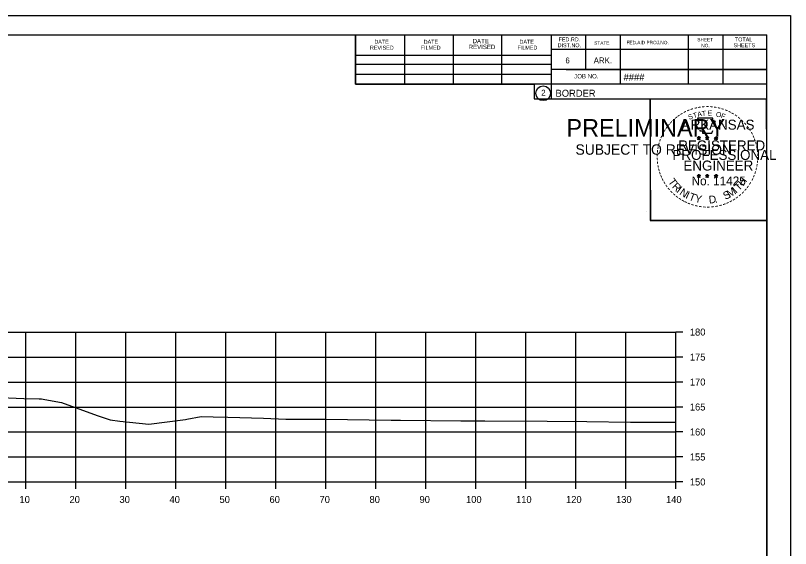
# Model space of a CAD drawing. Extents: x 1368503 to 1373085, y 379840 to 381833.
# Drawn here: x 1372930 to 1373085, y 381561.7 to 381668.3 of the extents above; entities that cross this region are included whole.
import ezdxf

# ---------------------------------------------------------------- set-up
doc = ezdxf.new("R2010")
doc.units = 0
for name, color, linetype in [('S_BRIDGE', 7, 'Continuous'), ('S_EDGE_PAVEMENT', 7, 'Continuous'), ('S_LANDSCAPING', 7, 'Continuous'), ('S_MISC_BOUNDARY', 7, 'Continuous'), ('S_MISC_BOUNDARY_ANNOT', 7, 'Continuous'), ('S_PHOTO_CENTERS', 7, 'Continuous'), ('S_PHOTO_NOTES', 7, 'Continuous'), ('S_TRAILS', 7, 'Continuous')]:
    doc.layers.add(name, color=color, linetype=linetype)

msp = doc.modelspace()

# ---------------------------------------------------------------- linework, layer by layer
at = {"layer": 'S_BRIDGE'}
for p, q in [((1372764.08, 381664.44), (1373080.26, 381664.44)), ((1372998, 381654.56), (1372998, 381664.44)), ((1373037.16, 381664.44), (1373037.16, 381651.64)), ((1373044, 381664.44), (1373044, 381657.5)), ((1373050.94, 381664.44), (1373050.94, 381654.56)), ((1373064.52, 381664.44), (1373064.52, 381654.56)), ((1373071.46, 381664.44), (1373071.46, 381654.56)), ((1373080.26, 381458.98), (1373080.26, 381664.44)), ((1373007.86, 381654.56), (1373007.86, 381664.24)), ((1373017.62, 381654.56), (1373017.62, 381664.24)), ((1373027.3, 381654.56), (1373027.3, 381664.24)), ((1373080.26, 381661.5), (1373037.16, 381661.5)), ((1373080.26, 381661.52), (1373080.26, 381661.52)), ((1372998, 381660.42), (1373037.16, 381660.42)), ((1372998, 381658.56), (1373037.16, 381658.56)), ((1372998, 381654.56), (1372998, 381656.62)), ((1372998, 381656.62), (1373037.16, 381656.62)), ((1373080.26, 381657.5), (1373037.16, 381657.5)), ((1373040.12, 381657.5), (1373080.26, 381657.5)), ((1373080.26, 381654.56), (1372998, 381654.56)), ((1373037.16, 381651.64), (1373080.26, 381651.64))]:
    msp.add_line(p, q, dxfattribs=at)
msp.add_circle((1373035.55, 381652.77), 1.47, dxfattribs=at)
at = {"layer": 'S_EDGE_PAVEMENT'}
for p, q in [((1373062.08, 381574.98), (1373062.08, 381604.98)), ((1373063.48, 381604.98), (1373062.08, 381604.98)), ((1373063.48, 381599.98), (1373062.08, 381599.98)), ((1373063.48, 381594.98), (1373062.08, 381594.98)), ((1373063.48, 381589.98), (1373062.08, 381589.98)), ((1373063.48, 381584.98), (1373062.08, 381584.98)), ((1373063.48, 381579.98), (1373062.08, 381579.98)), ((1372782.08, 381574.98), (1373062.08, 381574.98)), ((1372932.08, 381573.58), (1372932.08, 381574.98)), ((1372942.08, 381573.58), (1372942.08, 381574.98)), ((1372952.08, 381573.58), (1372952.08, 381574.98)), ((1372962.08, 381573.58), (1372962.08, 381574.98)), ((1372972.08, 381573.58), (1372972.08, 381574.98)), ((1372982.08, 381573.58), (1372982.08, 381574.98)), ((1372992.08, 381573.58), (1372992.08, 381574.98)), ((1373002.08, 381573.58), (1373002.08, 381574.98)), ((1373012.08, 381573.58), (1373012.08, 381574.98)), ((1373022.08, 381573.58), (1373022.08, 381574.98)), ((1373032.08, 381573.58), (1373032.08, 381574.98)), ((1373042.08, 381573.58), (1373042.08, 381574.98)), ((1373052.08, 381573.58), (1373052.08, 381574.98)), ((1373062.08, 381573.58), (1373062.08, 381574.98)), ((1373063.48, 381574.98), (1373062.08, 381574.98))]:
    msp.add_line(p, q, dxfattribs=at)
at = {"layer": 'S_LANDSCAPING'}
for p, q in [((1373066.35, 381643.89), (1373066.7, 381643.78)), ((1373066.35, 381643.89), (1373066.6, 381643.85)), ((1373066.35, 381643.89), (1373066.58, 381643.77)), ((1373066.48, 381643.48), (1373066.7, 381643.78)), ((1373066.48, 381643.48), (1373066.61, 381643.73)), ((1373066.48, 381643.48), (1373066.69, 381643.7)), ((1373066.7, 381644.15), (1373066.65, 381643.89)), ((1373066.91, 381643.48), (1373066.69, 381643.7)), ((1373066.7, 381643.78), (1373066.7, 381644.15)), ((1373066.7, 381644.15), (1373066.74, 381643.9)), ((1373067.04, 381643.89), (1373066.7, 381643.78)), ((1373066.91, 381643.48), (1373066.7, 381643.78)), ((1373067.04, 381643.89), (1373066.76, 381643.84)), ((1373066.91, 381643.48), (1373066.77, 381643.78)), ((1373067.04, 381643.89), (1373066.84, 381643.79)), ((1373068.02, 381643.89), (1373068.37, 381643.78)), ((1373068.02, 381643.89), (1373068.27, 381643.85)), ((1373068.02, 381643.89), (1373068.25, 381643.77)), ((1373068.15, 381643.48), (1373068.37, 381643.78)), ((1373068.15, 381643.48), (1373068.28, 381643.73)), ((1373068.15, 381643.48), (1373068.36, 381643.7)), ((1373068.37, 381644.15), (1373068.32, 381643.89)), ((1373068.58, 381643.48), (1373068.36, 381643.7)), ((1373068.37, 381643.78), (1373068.37, 381644.15)), ((1373068.37, 381644.15), (1373068.41, 381643.9)), ((1373068.71, 381643.89), (1373068.37, 381643.78)), ((1373068.58, 381643.48), (1373068.37, 381643.78)), ((1373068.71, 381643.89), (1373068.43, 381643.84)), ((1373068.58, 381643.48), (1373068.44, 381643.78)), ((1373068.71, 381643.89), (1373068.51, 381643.79)), ((1373069.78, 381643.88), (1373070.13, 381643.77)), ((1373069.78, 381643.88), (1373070.03, 381643.84)), ((1373069.78, 381643.88), (1373070.02, 381643.76)), ((1373069.91, 381643.47), (1373070.13, 381643.77)), ((1373069.91, 381643.47), (1373070.04, 381643.72)), ((1373069.91, 381643.47), (1373070.13, 381643.69)), ((1373070.13, 381644.13), (1373070.09, 381643.88)), ((1373070.13, 381643.77), (1373070.13, 381644.13)), ((1373070.13, 381644.13), (1373070.18, 381643.88)), ((1373070.48, 381643.88), (1373070.13, 381643.77)), ((1373070.34, 381643.47), (1373070.13, 381643.77)), ((1373070.34, 381643.47), (1373070.13, 381643.69)), ((1373070.48, 381643.88), (1373070.19, 381643.83)), ((1373070.34, 381643.47), (1373070.21, 381643.76)), ((1373070.48, 381643.88), (1373070.27, 381643.78)), ((1373066.69, 381636.57), (1373066.65, 381636.32)), ((1373066.69, 381636.21), (1373066.69, 381636.57)), ((1373066.69, 381636.57), (1373066.74, 381636.32)), ((1373068.36, 381636.57), (1373068.32, 381636.32)), ((1373068.36, 381636.21), (1373068.36, 381636.57)), ((1373068.36, 381636.57), (1373068.41, 381636.32)), ((1373070.13, 381636.56), (1373070.09, 381636.31)), ((1373070.13, 381636.2), (1373070.13, 381636.56)), ((1373070.13, 381636.56), (1373070.18, 381636.31)), ((1373066.34, 381636.32), (1373066.69, 381636.21)), ((1373066.34, 381636.32), (1373066.6, 381636.27)), ((1373066.34, 381636.32), (1373066.58, 381636.2)), ((1373066.48, 381635.91), (1373066.69, 381636.21)), ((1373066.48, 381635.91), (1373066.6, 381636.16)), ((1373066.48, 381635.91), (1373066.69, 381636.13)), ((1373067.04, 381636.32), (1373066.69, 381636.21)), ((1373066.9, 381635.91), (1373066.69, 381636.21)), ((1373066.9, 381635.91), (1373066.69, 381636.13)), ((1373067.04, 381636.32), (1373066.75, 381636.27)), ((1373066.9, 381635.91), (1373066.77, 381636.2)), ((1373067.04, 381636.32), (1373066.83, 381636.22)), ((1373068.01, 381636.32), (1373068.36, 381636.21)), ((1373068.01, 381636.32), (1373068.26, 381636.27)), ((1373068.01, 381636.32), (1373068.25, 381636.2)), ((1373068.14, 381635.91), (1373068.36, 381636.21)), ((1373068.14, 381635.91), (1373068.27, 381636.16)), ((1373068.14, 381635.91), (1373068.36, 381636.13)), ((1373068.71, 381636.32), (1373068.36, 381636.21)), ((1373068.57, 381635.91), (1373068.36, 381636.21)), ((1373068.57, 381635.91), (1373068.36, 381636.13)), ((1373068.71, 381636.32), (1373068.42, 381636.27)), ((1373068.57, 381635.91), (1373068.44, 381636.2)), ((1373068.71, 381636.32), (1373068.5, 381636.22)), ((1373069.78, 381636.31), (1373070.13, 381636.2)), ((1373069.78, 381636.31), (1373070.03, 381636.26)), ((1373069.78, 381636.31), (1373070.02, 381636.19)), ((1373069.91, 381635.9), (1373070.13, 381636.2)), ((1373069.91, 381635.9), (1373070.04, 381636.15)), ((1373069.91, 381635.9), (1373070.13, 381636.12)), ((1373070.47, 381636.31), (1373070.13, 381636.2)), ((1373070.34, 381635.9), (1373070.13, 381636.2)), ((1373070.34, 381635.9), (1373070.13, 381636.12)), ((1373070.47, 381636.31), (1373070.19, 381636.26)), ((1373070.34, 381635.9), (1373070.2, 381636.19)), ((1373070.47, 381636.31), (1373070.27, 381636.21))]:
    msp.add_line(p, q, dxfattribs=at)
for points in [[(1373066.39, 381647.77), (1373066.66, 381646.94)], [(1373069.9, 381646.85), (1373070.04, 381647.13), (1373069.36, 381647.11), (1373069.5, 381647.77), (1373066.39, 381647.77)], [(1373066.88, 381645.35), (1373066.88, 381645.26), (1373067.44, 381645.24), (1373067.39, 381644.77), (1373069.26, 381644.77), (1373069.46, 381645.3)], [(1373066.7, 381644.15), (1373066.91, 381643.48), (1373066.35, 381643.89), (1373067.04, 381643.89), (1373066.48, 381643.48), (1373066.7, 381644.15)], [(1373068.37, 381644.15), (1373068.58, 381643.48), (1373068.02, 381643.89), (1373068.71, 381643.89), (1373068.15, 381643.48), (1373068.37, 381644.15)], [(1373070.13, 381644.13), (1373070.34, 381643.47), (1373069.78, 381643.88), (1373070.48, 381643.88), (1373069.91, 381643.47), (1373070.13, 381644.13)], [(1373066.69, 381636.57), (1373066.9, 381635.91), (1373066.34, 381636.32), (1373067.04, 381636.32), (1373066.48, 381635.91), (1373066.69, 381636.57)], [(1373068.36, 381636.57), (1373068.57, 381635.91), (1373068.01, 381636.32), (1373068.71, 381636.32), (1373068.14, 381635.91), (1373068.36, 381636.57)], [(1373070.13, 381636.56), (1373070.34, 381635.9), (1373069.78, 381636.31), (1373070.47, 381636.31), (1373069.91, 381635.9), (1373070.13, 381636.56)]]:
    msp.add_lwpolyline(points, dxfattribs=at)
for centre, radius in [((1373066.69, 381643.78), 0.172), ((1373066.69, 381643.78), 0.145), ((1373066.69, 381643.78), 0.116), ((1373066.69, 381643.78), 0.0991), ((1373066.69, 381643.78), 0.0747), ((1373066.69, 381643.78), 0.0495), ((1373066.69, 381643.78), 0.0296), ((1373068.36, 381643.78), 0.172), ((1373068.36, 381643.78), 0.145), ((1373068.36, 381643.78), 0.116), ((1373068.36, 381643.78), 0.0991), ((1373068.36, 381643.78), 0.0747), ((1373068.36, 381643.78), 0.0495), ((1373068.36, 381643.78), 0.0296), ((1373070.13, 381643.77), 0.172), ((1373070.13, 381643.77), 0.145), ((1373070.13, 381643.77), 0.116), ((1373070.13, 381643.77), 0.0991), ((1373070.13, 381643.77), 0.0747), ((1373070.13, 381643.77), 0.0495), ((1373070.13, 381643.77), 0.0296), ((1373066.69, 381636.21), 0.172), ((1373066.69, 381636.21), 0.145), ((1373066.69, 381636.21), 0.116), ((1373066.69, 381636.21), 0.0991), ((1373066.69, 381636.21), 0.0747), ((1373066.69, 381636.21), 0.0495), ((1373066.69, 381636.21), 0.0296), ((1373068.36, 381636.21), 0.172), ((1373068.36, 381636.21), 0.145), ((1373068.36, 381636.21), 0.116), ((1373068.36, 381636.21), 0.0991), ((1373068.36, 381636.21), 0.0747), ((1373068.36, 381636.21), 0.0495), ((1373068.36, 381636.21), 0.0296), ((1373070.13, 381636.2), 0.172), ((1373070.13, 381636.2), 0.145), ((1373070.13, 381636.2), 0.116), ((1373070.13, 381636.2), 0.0991), ((1373070.13, 381636.2), 0.0747), ((1373070.13, 381636.2), 0.0495), ((1373070.13, 381636.2), 0.0296)]:
    msp.add_circle(centre, radius, dxfattribs=at)
at = {"layer": 'S_MISC_BOUNDARY'}
msp.add_lwpolyline([(1372925.58, 381591.97), (1372931.69, 381591.71), (1372934.75, 381591.62), (1372935.23, 381591.61), (1372935.9, 381591.48), (1372939.23, 381590.85), (1372946.36, 381588.31), (1372948.93, 381587.39), (1372950.86, 381587.18), (1372956.7, 381586.56), (1372963.52, 381587.41), (1372964.02, 381587.48), (1372964.26, 381587.52), (1372967.14, 381588.05), (1372969.57, 381588), (1372972.48, 381587.95), (1372979.64, 381587.72), (1372984.07, 381587.56), (1372991.26, 381587.56), (1372991.61, 381587.56), (1372992.02, 381587.56), (1373005.13, 381587.35), (1373007.03, 381587.35), (1373019.09, 381587.24), (1373023.86, 381587.21), (1373036.36, 381587.15), (1373044.26, 381587.07), (1373053.03, 381586.97), (1373062.08, 381586.92)], dxfattribs=at)
at = {"layer": 'S_PHOTO_CENTERS'}
for p, q in [((1372782.08, 381604.98), (1373062.08, 381604.98)), ((1372932.08, 381574.98), (1372932.08, 381604.98)), ((1372942.08, 381574.98), (1372942.08, 381604.98)), ((1372952.08, 381574.98), (1372952.08, 381604.98)), ((1372962.08, 381574.98), (1372962.08, 381604.98)), ((1372972.08, 381574.98), (1372972.08, 381604.98)), ((1372982.08, 381574.98), (1372982.08, 381604.98)), ((1372992.08, 381574.98), (1372992.08, 381604.98)), ((1373002.08, 381574.98), (1373002.08, 381604.98)), ((1373012.08, 381574.98), (1373012.08, 381604.98)), ((1373022.08, 381574.98), (1373022.08, 381604.98)), ((1373032.08, 381574.98), (1373032.08, 381604.98)), ((1373042.08, 381574.98), (1373042.08, 381604.98)), ((1373052.08, 381574.98), (1373052.08, 381604.98)), ((1373062.08, 381574.98), (1373062.08, 381604.98)), ((1372782.08, 381599.98), (1373062.08, 381599.98)), ((1372782.08, 381594.98), (1373062.08, 381594.98)), ((1372782.08, 381589.98), (1373062.08, 381589.98)), ((1372782.08, 381584.98), (1373062.08, 381584.98)), ((1372782.08, 381579.98), (1373062.08, 381579.98)), ((1372782.08, 381574.98), (1373062.08, 381574.98))]:
    msp.add_line(p, q, dxfattribs=at)
at = {"layer": 'S_PHOTO_NOTES'}
for p, q in [((1372751.68, 381668.33), (1373085.01, 381668.33)), ((1373056.3, 381629.18), (1373056.3, 381629.18))]:
    msp.add_line(p, q, dxfattribs=at)
for points in [[(1372751.67, 381668.33), (1373085.01, 381668.33), (1373085.01, 381454.99), (1372751.67, 381454.99)], [(1372998, 381664.44), (1372998, 381654.56), (1373033.73, 381654.56), (1373033.73, 381651.64), (1373056.93, 381651.64), (1373056.93, 381627.3), (1373080.26, 381627.3), (1373080.26, 381458.98), (1372764.08, 381458.98), (1372764.08, 381664.44)], [(1373056.93, 381651.64), (1373080.14, 381651.64), (1373080.26, 381627.3), (1373057.05, 381627.3)]]:
    msp.add_lwpolyline(points, close=True, dxfattribs=at)

# ---------------------------------------------------------------- texts
at = {"layer": 'S_BRIDGE'}
for s, height, p in [('DATE', 0.782, (1373001.8, 381662.68)), ('DATE', 0.782, (1373011.66, 381662.68)), ('DATE', 0.879, (1373021.44, 381662.78)), ('DATE', 0.782, (1373030.82, 381662.68)), ('FED.RD.', 0.782, (1373038.64, 381663.16)), ('STATE', 0.684, (1373045.76, 381662.48)), ('FED.AID PROJ.NO.', 0.684, (1373052.22, 381662.58)), ('SHEET', 0.684, (1373066.38, 381663.16)), ('TOTAL', 0.782, (1373073.9, 381663.16)), ('REVISED', 0.782, (1373000.92, 381661.5)), ('FILMED', 0.782, (1373011.08, 381661.5)), ('REVISED', 0.879, (1373020.66, 381661.6)), ('FILMED', 0.782, (1373030.42, 381661.5)), ('DIST.NO.', 0.782, (1373038.44, 381661.98)), ('NO.', 0.684, (1373067.16, 381661.98)), ('SHEETS', 0.782, (1373073.62, 381661.98)), ('6', 1.17, (1373040, 381658.76)), ('ARK.', 1.172, (1373045.66, 381658.76)), ('JOB NO.', 0.879, (1373041.76, 381655.74)), ('####', 1.4, (1373051.64, 381655.3)), ('BORDER', 1.4, (1373038.02, 381652.07)), ('2', 1.17, (1373035.17, 381652.29))]:
    msp.add_text(s, height=height, rotation=360, dxfattribs=at).set_placement(p)
at = {"layer": 'S_LANDSCAPING'}
for s, height, rotation, p in [('-', 1.6, 34.0636, (1373063.27, 381647.94)), ('-', 1.6, 28.7918, (1373063.87, 381648.31)), ('-', 1.6, 24.3072, (1373064.5, 381648.63)), ('-', 1.6, 19.1761, (1373065.14, 381648.9)), ('T', 1, 16.4036, (1373065.66, 381647.78)), ('-', 1.6, 13.6301, (1373065.89, 381649.14)), ('A', 1, 11.2132, (1373066.48, 381648.03)), ('-', 1.6, 10.2193, (1373066.56, 381649.3)), ('T', 1, 6.0228, (1373067.33, 381648.2)), ('-', 1.6, 5.8968, (1373067.29, 381649.41)), ('-', 1.6, 0.1862, (1373068.06, 381649.48)), ('E', 1, 0.8323, (1373068.44, 381648.31)), ('-', 1.6, 357.743, (1373068.79, 381649.47)), ('-', 1.6, 352.1617, (1373069.53, 381649.41)), ('O', 1, 350.4515, (1373070.04, 381648.1)), ('-', 1.6, 347.2049, (1373070.25, 381649.3)), ('-', 1.6, 342.3362, (1373070.89, 381649.14)), ('-', 1.6, 337.8551, (1373071.62, 381648.92)), ('-', 1.6, 334.1211, (1373072.25, 381648.65)), ('-', 1.6, 329.6409, (1373072.83, 381648.37)), ('-', 1.6, 42.9622, (1373061.78, 381646.75)), ('-', 1.6, 38.9507, (1373062.22, 381647.17)), ('-', 1.6, 36.2317, (1373062.69, 381647.55)), ('ARKANSAS', 2, 360, (1373063.24, 381645.48)), ('S', 1, 21.594, (1373064.74, 381647.45)), ('F', 1, 340.0707, (1373070.99, 381647.87)), ('-', 1.6, 325.8627, (1373073.47, 381648.01)), ('-', 1.6, 320.5297, (1373074.08, 381647.58)), ('-', 1.6, 315.5786, (1373074.68, 381647.09)), ('-', 1.6, 54.2325, (1373060.52, 381645.22)), ('-', 1.6, 50.6142, (1373060.93, 381645.79)), ('-', 1.6, 48.423, (1373061.34, 381646.27)), ('-', 1.6, 309.8797, (1373075.25, 381646.54)), ('-', 1.6, 306.6522, (1373075.78, 381645.94)), ('-', 1.6, 67.7743, (1373059.62, 381643.47)), ('-', 1.6, 62.8713, (1373059.88, 381644.08)), ('-', 1.6, 58.0706, (1373060.2, 381644.69)), ('-', 1.4, 303.6753, (1373076.26, 381645.37)), ('-', 1.6, 299.6684, (1373076.58, 381644.77)), ('-', 1.6, 294.6628, (1373076.91, 381644.15)), ('-', 1.6, 75.461, (1373059.21, 381642.12)), ('-', 1.6, 72.3945, (1373059.4, 381642.84)), ('REGISTERED', 2, 360, (1373062.56, 381641.33)), ('DWB', 0.01, 360, (1373066.68, 381643.78)), ('DWB', 0.01, 360, (1373068.35, 381643.78)), ('DWB', 0.01, 360, (1373070.12, 381643.77)), ('-', 1.6, 290.5728, (1373077.16, 381643.58)), ('-', 1.6, 285.1233, (1373077.4, 381643)), ('-', 1.6, 85.1863, (1373059, 381640.72)), ('-', 1.6, 81.2013, (1373059.08, 381641.41)), ('PROFESSIONAL', 2, 360, (1373061.41, 381639.43)), ('-', 1.6, 280.5493, (1373077.6, 381642.25)), ('-', 1.6, 276.5962, (1373077.76, 381641.49)), ('-', 1.6, 94.1959, (1373059.01, 381639.29)), ('-', 1.6, 89.0622, (1373058.97, 381640.02)), ('-', 1.6, 274.3301, (1373077.82, 381640.76)), ('-', 1.6, 269.9407, (1373077.85, 381640.13)), ('-', 1.6, 98.9479, (1373059.08, 381638.63)), ('-', 1.6, 101.7149, (1373059.22, 381637.89)), ('ENGINEER', 2, 360, (1373063.6, 381637.3)), ('-', 1.6, 260.9953, (1373077.76, 381638.81)), ('-', 1.6, 263.5172, (1373077.83, 381639.47)), ('-', 1.6, 105.4578, (1373059.38, 381637.3)), ('-', 1.6, 109.0874, (1373059.59, 381636.67)), ('-', 1.6, 247.8887, (1373077.25, 381636.74)), ('-', 1.6, 252.8681, (1373077.47, 381637.41)), ('-', 1.6, 255.7626, (1373077.65, 381638.13)), ('-', 1.6, 114.0643, (1373059.85, 381636.07)), ('-', 1.6, 115.7289, (1373060.15, 381635.45)), ('-', 1.6, 120.4471, (1373060.51, 381634.87)), ('T', 1.54, 306.0406, (1373060.45, 381635.05)), ('R', 1.54, 314.005, (1373061.21, 381634)), ('No. 11425', 1.757, 360, (1373065.23, 381634.35)), ('DWB', 0.01, 360, (1373066.68, 381636.2)), ('DWB', 0.01, 360, (1373068.35, 381636.2)), ('DWB', 0.01, 360, (1373070.11, 381636.19)), ('T', 1.54, 46.6444, (1373074.68, 381633.14)), ('H', 1.54, 54.6088, (1373075.57, 381634.08)), ('-', 1.6, 239.0712, (1373076.59, 381635.36)), ('-', 1.6, 244.6197, (1373076.99, 381636.11)), ('-', 1.6, 125.8934, (1373060.91, 381634.31)), ('-', 1.6, 130.7181, (1373061.37, 381633.76)), ('I', 1.54, 321.9694, (1373062.11, 381633.07)), ('N', 1.54, 326.5002, (1373062.68, 381632.6)), ('M', 1.54, 32.6563, (1373072.84, 381631.81)), ('I', 1.54, 42.1136, (1373074.12, 381632.66)), ('-', 1.6, 231.2538, (1373075.76, 381634.14)), ('-', 1.6, 233.8452, (1373076.19, 381634.71)), ('-', 1.6, 134.2238, (1373061.89, 381633.21)), ('-', 1.6, 138.9338, (1373062.42, 381632.75)), ('-', 1.6, 144.6463, (1373062.97, 381632.34)), ('-', 1.6, 148.0898, (1373063.53, 381631.97)), ('I', 1.54, 335.3603, (1373063.89, 381631.81)), ('T', 1.54, 339.8912, (1373064.55, 381631.48)), ('Y', 1.54, 347.8556, (1373065.77, 381631.04)), ('D', 1.54, 6.3969, (1373068.75, 381630.68)), ('S', 1.54, 26.9312, (1373072, 381631.41)), ('-', 1.6, 215.7363, (1373074.21, 381632.6)), ('-', 1.6, 221.0851, (1373074.76, 381633.07)), ('-', 1.6, 225.7653, (1373075.28, 381633.58)), ('-', 1.6, 151.5704, (1373064.11, 381631.64)), ('-', 1.6, 154.6002, (1373064.63, 381631.4)), ('-', 1.6, 158.5612, (1373065.26, 381631.14)), ('-', 1.6, 162.7983, (1373065.95, 381630.93)), ('-', 1.6, 167.5555, (1373066.66, 381630.77)), ('-', 1.6, 191.2858, (1373070.47, 381630.83)), ('.', 1.54, 13.7642, (1373069.94, 381630.81)), ('-', 1.6, 195.4743, (1373071.2, 381631.03)), ('-', 1.6, 200.7184, (1373071.88, 381631.27)), ('-', 1.6, 204.2516, (1373072.49, 381631.54)), ('-', 1.6, 207.3568, (1373073.12, 381631.86)), ('-', 1.6, 212.2491, (1373073.68, 381632.21)), ('-', 1.6, 173.1155, (1373067.43, 381630.66)), ('-', 1.6, 176.5183, (1373068.18, 381630.6)), ('-', 1.6, 181.5918, (1373068.92, 381630.62)), ('-', 1.6, 185.8167, (1373069.73, 381630.7))]:
    msp.add_text(s, height=height, rotation=rotation, dxfattribs=at).set_placement(p)
at = {"layer": 'S_MISC_BOUNDARY_ANNOT'}
for s, height, p in [('PRELIMINARY', 3.5, (1373040.21, 381644.1)), ('DWB', 0.01, (1373040.96, 381645.95)), ('SUBJECT TO REVISION', 2.0751, (1373042.02, 381640.47))]:
    msp.add_text(s, height=height, rotation=360, dxfattribs=at).set_placement(p)
at = {"layer": 'S_TRAILS'}
for s, p in [('180', (1373064.88, 381604.28)), ('175', (1373064.88, 381599.28)), ('170', (1373064.88, 381594.28)), ('165', (1373064.88, 381589.28)), ('160', (1373064.88, 381584.28)), ('155', (1373064.88, 381579.28)), ('150', (1373064.88, 381574.28)), ('10', (1372930.82, 381570.78)), ('20', (1372940.82, 381570.78)), ('30', (1372950.82, 381570.78)), ('40', (1372960.82, 381570.78)), ('50', (1372970.82, 381570.78)), ('60', (1372980.82, 381570.78)), ('70', (1372990.82, 381570.78)), ('80', (1373000.82, 381570.78)), ('90', (1373010.82, 381570.78)), ('100', (1373020.12, 381570.78)), ('110', (1373030.12, 381570.78)), ('120', (1373040.12, 381570.78)), ('130', (1373050.12, 381570.78)), ('140', (1373060.12, 381570.78))]:
    msp.add_text(s, height=1.4, dxfattribs=at).set_placement(p)

doc.saveas('drawing.dxf')
